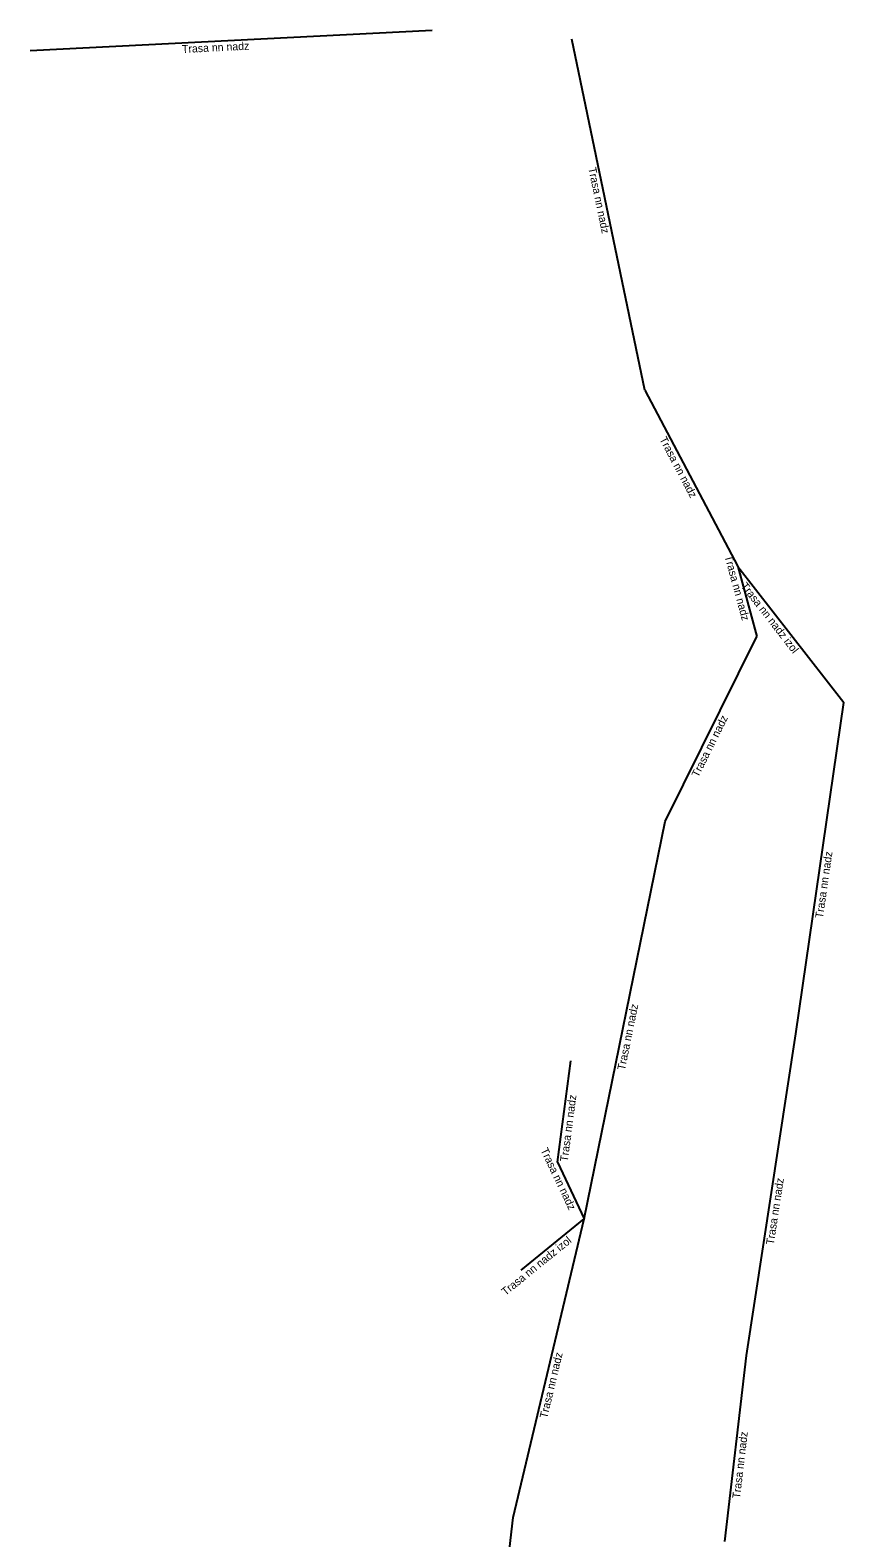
# Model space of a CAD drawing. Extents: x -772942 to -772530, y -1033745 to -1033298.
# Drawn here: x -772847.9 to -772796.2, y -1033402.1 to -1033306.4 of the extents above; entities that cross this region are included whole.
import ezdxf

# ---------------------------------------------------------------- set-up
doc = ezdxf.new("R2010")
doc.units = 0
doc.layers.add('Popiskový text - Ostatní atributy Trasy', color=7, linetype='Continuous')
doc.layers.add('Spojnice NN', color=7, linetype='Continuous')

msp = doc.modelspace()

# ---------------------------------------------------------------- linework, layer by layer
at = {"layer": 'Spojnice NN'}
for points in [[(-772847.854, -1033307.721), (-772822.338, -1033306.432)], [(-772808.847, -1033329.272), (-772813.484, -1033307.003)], [(-772808.847, -1033329.272), (-772802.949, -1033340.462)], [(-772802.949, -1033340.462), (-772801.741, -1033344.915)], [(-772802.949, -1033340.462), (-772796.226, -1033349.096)], [(-772807.553, -1033356.635), (-772801.741, -1033344.915)], [(-772799.272, -1033370.112), (-772796.226, -1033349.096)], [(-772812.7, -1033381.862), (-772807.553, -1033356.635)], [(-772802.408, -1033390.528), (-772799.272, -1033370.112)], [(-772814.403, -1033378.256), (-772813.558, -1033371.841)], [(-772814.403, -1033378.256), (-772812.7, -1033381.862)], [(-772817.209, -1033400.814), (-772812.7, -1033381.862)], [(-772816.701, -1033385.111), (-772812.7, -1033381.862)], [(-772803.783, -1033402.328), (-772802.408, -1033390.528)], [(-772818.393, -1033411.073), (-772817.209, -1033400.814)]]:
    msp.add_lwpolyline(points, dxfattribs=at)

# ---------------------------------------------------------------- texts
at = {"layer": 'Popiskový text - Ostatní atributy Trasy'}
for s, rotation, p in [('Trasa nn nadz', 2.89197, (-772838.207, -1033307.884)), ('Trasa nn nadz', 281.76243, (-772812.443, -1033315.188)), ('Trasa nn nadz', 297.79272, (-772807.941, -1033332.386)), ('Trasa nn nadz', 285.17779, (-772803.796, -1033339.821)), ('Trasa nn nadz izol', 307.90667, (-772802.797, -1033341.715)), ('Trasa nn nadz', 63.62298, (-772805.463, -1033353.884)), ('Trasa nn nadz', 81.75314, (-772797.557, -1033362.812)), ('Trasa nn nadz', 78.46836, (-772810.119, -1033372.462)), ('Trasa nn nadz', 82.49606, (-772813.747, -1033378.254)), ('Trasa nn nadz', 295.27989, (-772815.483, -1033377.491)), ('Trasa nn nadz', 81.26733, (-772800.676, -1033383.53)), ('Trasa nn nadz izol', 39.07566, (-772817.698, -1033386.758)), ('Trasa nn nadz', 76.61718, (-772815.05, -1033394.551)), ('Trasa nn nadz', 83.35356, (-772802.814, -1033399.629))]:
    msp.add_text(s, height=0.5, rotation=rotation, dxfattribs=at).set_placement(p)

doc.saveas('drawing.dxf')
